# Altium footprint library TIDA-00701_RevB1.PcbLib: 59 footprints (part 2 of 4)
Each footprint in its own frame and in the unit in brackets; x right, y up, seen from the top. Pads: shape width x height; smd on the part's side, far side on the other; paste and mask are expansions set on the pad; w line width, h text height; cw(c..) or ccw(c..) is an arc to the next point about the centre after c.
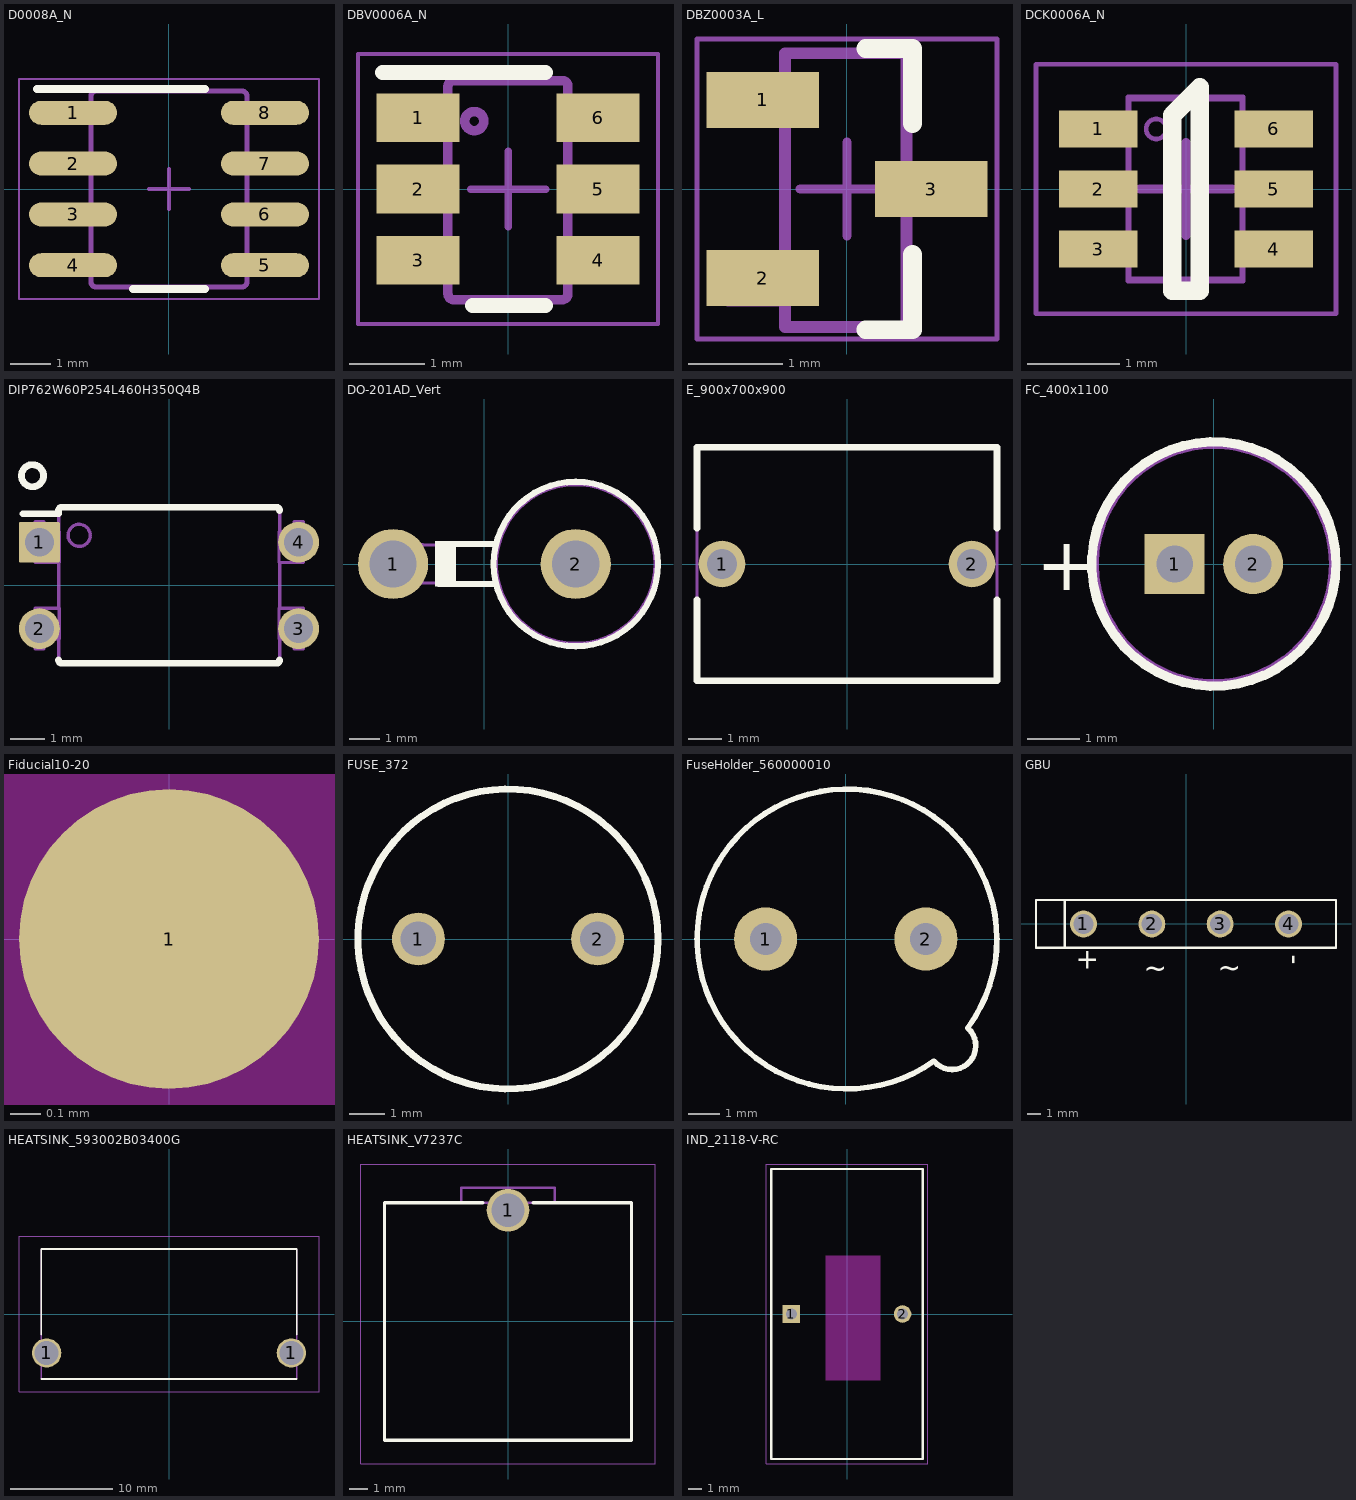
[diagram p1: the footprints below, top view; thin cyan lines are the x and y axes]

## D0008A_N [mm] "SOIC, 8-Leads, Body 4.9x3.9mm, Pitch 1.27mm, IPC Medium Density"
height 1.75
pads (8):
  oval 2.2x0.6 smd: 1(-2.4,1.905) 2(-2.4,0.635) 3(-2.4,-0.635) 4(-2.4,-1.905) 5(2.4,-1.905) 6(2.4,-0.635) 7(2.4,0.635) 8(2.4,1.905)
Top Overlay:
  lines w0.2: -3.3,2.5 0.9,2.5 ; -0.9,-2.5 0.9,-2.5
Mechanical 5:
  lines w0.127: -2.375,-2.095 -1.995,-2.095 -1.952,-2.095 -1.952,-1.715 -1.995,-1.715 -2.375,-1.715 ; -2.375,-2.095 -2.589,-2.095 -3.002,-2.095 -3.002,-1.715 -2.589,-1.715 -2.375,-1.715 ; -2.375,-2.095 -2.375,-1.715 ; -2.375,-0.825 -1.995,-0.825 -1.952,-0.825 -1.952,-0.445 -1.995,-0.445 -2.375,-0.445 ; -2.375,-0.825 -2.589,-0.825 -3.002,-0.825 -3.002,-0.445 -2.589,-0.445 -2.375,-0.445 ; -2.375,-0.825 -2.375,-0.445 ; -2.375,0.445 -1.995,0.445 -1.952,0.445 -1.952,0.825 -1.995,0.825 -2.375,0.825 ; -2.375,0.445 -2.589,0.445 -3.002,0.445 -3.002,0.825 -2.589,0.825 -2.375,0.825 ; -2.375,0.445 -2.375,0.825 ; -2.375,1.715 -1.995,1.715 -1.952,1.715 -1.952,2.095 -1.995,2.095 -2.375,2.095 ; -2.375,1.715 -2.589,1.715 -3.002,1.715 -3.002,2.095 -2.589,2.095 -2.375,2.095 ; -2.375,1.715 -2.375,2.095 ; -0.332,-2.45 -1.825,-2.45 -1.826,-2.45 cw(c-1.825,-2.323) -1.952,-2.324 -1.952,-2.323 -1.952,2.323 -1.952,2.324 cw(c-1.825,2.323) -1.826,2.45 -1.825,2.45 -0.332,2.45 ; -0.332,-2.45 -0.182,-2.45 ; -0.332,-2.45 -0.182,-2.45 ; -0.332,2.45 -0.182,2.45 ; -0.332,2.45 -0.182,2.45 ; -0.182,-2.45 0.178,-2.45 ; -0.182,2.45 0.178,2.45 ; 0.178,-2.45 0.328,-2.45 ; 0.178,-2.45 0.328,-2.45 ; 0.178,2.45 0.328,2.45 ; 0.178,2.45 0.328,2.45 ; 0.328,-2.45 1.821,-2.45 1.822,-2.45 ccw(c1.821,-2.323) 1.948,-2.324 1.948,-2.323 1.948,2.323 1.948,2.324 ccw(c1.821,2.323) 1.822,2.45 1.821,2.45 0.328,2.45 ; 2.371,-2.095 2.585,-2.095 2.998,-2.095 2.998,-1.715 2.585,-1.715 2.371,-1.715 ; 2.371,-2.095 1.991,-2.095 1.948,-2.095 1.948,-1.715 1.991,-1.715 2.371,-1.715 ; 2.371,-2.095 2.371,-1.715 ; 2.371,-0.825 2.585,-0.825 2.998,-0.825 2.998,-0.445 2.585,-0.445 2.371,-0.445 ; 2.371,-0.825 1.991,-0.825 1.948,-0.825 1.948,-0.445 1.991,-0.445 2.371,-0.445 ; 2.371,-0.825 2.371,-0.445 ; 2.371,0.445 2.585,0.445 2.998,0.445 2.998,0.825 2.585,0.825 2.371,0.825 ; 2.371,0.445 1.991,0.445 1.948,0.445 1.948,0.825 1.991,0.825 2.371,0.825 ; 2.371,0.445 2.371,0.825 ; 2.371,1.715 2.585,1.715 2.998,1.715 2.998,2.095 2.585,2.095 2.371,2.095 ; 2.371,1.715 1.991,1.715 1.948,1.715 1.948,2.095 1.991,2.095 2.371,2.095 ; 2.371,1.715 2.371,2.095
  text ".Designator" at 0.452,-0.439 h0.89
Mechanical 15:
  lines w0.05: -3.75,-2.75 -3.75,2.75 3.75,2.75 3.75,-2.75 -3.75,-2.75
  lines w0.1: -0.5,0 0.5,0 ; 0,-0.5 0,0.5
3D body: height 1.63, standoff 0, extent -3,-2.45 3,2.45

## DBV0006A_N [mm] "SOT23, 6-Leads, Body 2.9x1.6mm, Pitch 0.95mm, Lead Span 2.8mm, IPC Medium Density"
height 1.45
pads (6):
  rect 1.1x0.65 smd: 1(-1.2,0.95) 2(-1.2,0) 3(-1.2,-0.95) 4(1.2,-0.95) 5(1.2,0) 6(1.2,0.95)
Top Overlay:
  lines w0.2: -1.675,1.55 0.5,1.55 ; -0.475,-1.55 0.5,-1.55
Mechanical 5:
  lines w0.127: 0.724,-1.475 ccw(c0.723,-1.399) 0.8,-1.399 0.799,1.37 ccw(c0.723,1.37) 0.724,1.446 ; 0.723,-1.475 -0.725,-1.475 -0.725,-1.475 cw(c-0.724,-1.399) -0.801,-1.399 -0.801,1.37 cw(c-0.724,1.37) -0.725,1.446 -0.725,1.446 0.723,1.446 ; 0.723,-1.475 0.724,-1.475 ; 0.723,1.446 0.724,1.446 ; -1.423,-1.154 -1.423,-0.78 -1.206,-0.78 -1.113,-0.78 -1.081,-0.78 -0.828,-0.78 -0.801,-0.78 -0.801,-1.154 -0.828,-1.154 -1.081,-1.154 -1.113,-1.154 -1.206,-1.154 -1.423,-1.154 ; -1.423,-0.202 -1.423,0.173 -1.206,0.173 -1.113,0.173 -1.081,0.173 -0.828,0.173 -0.801,0.173 -0.801,-0.202 -0.828,-0.202 -1.081,-0.202 -1.113,-0.202 -1.206,-0.202 -1.423,-0.202 ; -1.423,0.751 -1.423,1.125 -1.206,1.125 -1.113,1.125 -1.081,1.125 -0.828,1.125 -0.801,1.125 -0.801,0.751 -0.828,0.751 -1.081,0.751 -1.113,0.751 -1.206,0.751 -1.423,0.751 ; -0.577,0.906 ccw(c-0.45,0.906) -0.323,0.906 ccw(c-0.45,0.906) -0.577,0.906 ; 0.799,-1.154 0.799,-0.78 0.827,-0.78 1.08,-0.78 1.112,-0.78 1.205,-0.78 1.422,-0.78 1.422,-1.154 1.205,-1.154 1.112,-1.154 1.08,-1.154 0.827,-1.154 0.799,-1.154 ; 0.799,-0.202 0.799,0.173 0.827,0.173 1.08,0.173 1.112,0.173 1.205,0.173 1.422,0.173 1.422,-0.202 1.205,-0.202 1.112,-0.202 1.08,-0.202 0.827,-0.202 0.799,-0.202 ; 0.799,0.751 0.799,1.125 0.827,1.125 1.08,1.125 1.112,1.125 1.205,1.125 1.422,1.125 1.422,0.751 1.205,0.751 1.112,0.751 1.08,0.751 0.827,0.751 0.799,0.751
  text ".Designator" at -0.356,0.457 h0.89
Mechanical 15:
  lines w0.05: -2,-1.8 2,-1.8 2,1.8 -2,1.8 -2,-1.8
  lines w0.1: -0.5,0 0.5,0 ; 0,-0.5 0,0.5
3D body: height 1.11, standoff -0.01, extent -1.422,-1.461 1.422,1.46

## DBZ0003A_L [mm] "SOT23, 3-Leads, Body 2.9x1.3mm, Pitch 0.95mm, Lead Span 2.4mm, IPC High Density"
height 1.12
pads (3):
  rect 1.2x0.6 smd: 1(-0.9,0.95) 2(-0.9,-0.95) 3(0.9,0)
Top Overlay:
  lines w0.2: 0.2,-1.5 0.7,-1.5 0.7,-0.7 ; 0.2,1.5 0.7,1.5 0.7,0.7
Mechanical 5:
  lines w0.127: -1.27,-1.187 -1.063,-1.187 -1.005,-1.187 -0.814,-1.187 -0.66,-1.187 -0.66,-0.743 -0.814,-0.743 -1.005,-0.743 -1.063,-0.743 -1.27,-0.743 -1.27,-1.187 ; -1.27,0.718 -1.063,0.718 -1.005,0.718 -0.814,0.718 -0.66,0.718 -0.66,1.162 -0.814,1.162 -1.005,1.162 -1.063,1.162 -1.27,1.162 -1.27,0.718 ; -0.66,-1.473 0.635,-1.473 0.635,1.448 -0.66,1.448 -0.66,-1.473 ; 0.635,-0.235 0.635,0.21 0.789,0.21 0.98,0.21 1.037,0.21 1.245,0.21 1.245,-0.235 1.037,-0.235 0.98,-0.235 0.789,-0.235 0.635,-0.235
  text ".Designator" at -0.457,0.635 h0.89
Mechanical 15:
  lines w0.05: -1.6,-1.6 -1.6,1.6 1.6,1.6 1.6,-1.6 -1.6,-1.6
  lines w0.1: -0.5,0 0.5,0 ; 0,-0.5 0,0.5
3D body: height 0.96, standoff -0.02, extent -1.257,-1.461 1.257,1.46

## DCK0006A_N [mm] "SOT23, 6-Leads, Body 2x1.3mm, Pitch 0.65mm, Lead Span 2.1mm, IPC Medium Density"
height 1.1
pads (6):
  rect 0.85x0.4 smd: 1(-0.95,0.65) 2(-0.95,0) 3(-0.95,-0.65) 4(0.95,-0.65) 5(0.95,0) 6(0.95,0.65)
Top Overlay:
  lines w0.2: -0.15,-1.1 0.15,-1.1 0.15,1.1 -0.15,0.8 -0.15,-1.1
Mechanical 5:
  lines w0.05: -0.613,-0.763 -0.613,-0.976 0.607,-0.976 0.607,-0.763 ; -0.613,-0.538 -0.613,-0.113 ; -0.613,0.112 -0.613,0.537 ; -0.613,0.762 -0.613,0.974 0.607,0.974 0.607,0.762 ; 0.607,-0.538 0.607,-0.113 ; 0.607,0.112 0.607,0.537 ; -0.628,-0.763 -0.591,-0.763 -0.591,-0.538 -0.628,-0.538 ; -0.628,-0.763 -0.853,-0.763 -0.865,-0.763 -0.959,-0.763 -1.143,-0.763 -1.143,-0.538 -0.959,-0.538 -0.865,-0.538 -0.853,-0.538 -0.628,-0.538 ; -0.628,-0.763 -0.628,-1.001 0.622,-1.001 0.622,-0.763 ; -0.628,-0.538 -0.628,-0.113 ; -0.628,-0.113 -0.591,-0.113 -0.591,0.112 -0.628,0.112 ; -0.628,-0.113 -0.853,-0.113 -0.865,-0.113 -0.959,-0.113 -1.143,-0.113 -1.143,0.112 -0.959,0.112 -0.865,0.112 -0.853,0.112 -0.628,0.112 ; -0.628,0.112 -0.628,0.537 ; -0.628,0.537 -0.591,0.537 -0.591,0.762 -0.628,0.762 ; -0.628,0.537 -0.853,0.537 -0.865,0.537 -0.959,0.537 -1.143,0.537 -1.143,0.762 -0.959,0.762 -0.865,0.762 -0.853,0.762 -0.628,0.762 ; -0.628,0.762 -0.628,0.999 0.622,0.999 0.622,0.762 ; 0.622,-0.763 0.585,-0.763 0.585,-0.538 0.622,-0.538 ; 0.622,-0.763 0.847,-0.763 0.859,-0.763 0.953,-0.763 1.137,-0.763 1.137,-0.538 0.953,-0.538 0.859,-0.538 0.847,-0.538 0.622,-0.538 ; 0.622,-0.538 0.622,-0.113 ; 0.622,-0.113 0.847,-0.113 0.859,-0.113 0.953,-0.113 1.137,-0.113 1.137,0.112 0.953,0.112 0.859,0.112 0.847,0.112 0.622,0.112 ; 0.622,-0.113 0.585,-0.113 0.585,0.112 0.622,0.112 ; 0.622,0.112 0.622,0.537 ; 0.622,0.537 0.585,0.537 0.585,0.762 0.622,0.762 ; 0.622,0.537 0.847,0.537 0.859,0.537 0.953,0.537 1.137,0.537 1.137,0.762 0.953,0.762 0.859,0.762 0.847,0.762 0.622,0.762 ; -0.432,0.65 ccw(c-0.323,0.65) -0.215,0.65 ccw(c-0.323,0.65) -0.432,0.65
  text ".Designator" at -1.524,-0.584 h0.89
Mechanical 15:
  lines w0.05: -1.625,-1.35 1.625,-1.35 1.625,1.35 -1.625,1.35 -1.625,-1.35
  lines w0.1: -0.5,0 0.5,0 ; 0,-0.5 0,0.5
3D body: height 0.94, standoff -0.01, extent -1.14,-1 1.14,1

## DIP762W60P254L460H350Q4B [mm] "LITE-ON"
height 4.5
pads (4):
  rrect8% 1.2x1.2 hole 0.85: 1(-3.81,1.27)
  round 1.2 hole 0.85: 2(-3.81,-1.27) 3(3.81,-1.27) 4(3.81,1.27)
Top Overlay:
  circle w0.2: c-4.013,3.226 r0.325
  lines w0.2: -4.293,2.108 -3.247,2.108 -3.247,2.201 cw(c-3.148,2.201) -3.148,2.3 3.154,2.3 cw(c3.154,2.201) 3.253,2.201 ; -3.247,-2.191 ccw(c-3.148,-2.192) -3.148,-2.29 3.154,-2.29 ccw(c3.154,-2.192) 3.253,-2.191
Mechanical 5:
  circle w0.1: c-2.642,1.473 r0.325
  lines w0.1: -3.677,-1.565 -3.677,-1.865 -3.937,-1.865 -3.937,-1.565 ; -3.677,1.575 -3.677,1.875 -3.937,1.875 -3.937,1.575 ; -3.247,-1.565 -3.247,-2.191 ccw(c-3.148,-2.192) -3.148,-2.29 3.154,-2.29 ccw(c3.154,-2.192) 3.253,-2.191 3.253,-1.565 ; -3.247,-0.665 -3.247,0.675 ; -3.247,1.575 -3.247,2.201 cw(c-3.148,2.201) -3.148,2.3 3.154,2.3 cw(c3.154,2.201) 3.253,2.201 3.253,1.575 ; 3.253,-0.665 3.253,0.675 ; 3.683,-1.565 3.683,-1.865 3.943,-1.865 3.943,-1.565 ; 3.683,1.575 3.683,1.875 3.943,1.875 3.943,1.575 ; -3.937,-1.565 -3.937,-0.665 -3.737,-0.665 -3.229,-0.665 -3.229,-1.565 -3.737,-1.565 -3.937,-1.565 ; -3.937,1.575 -3.937,0.675 -3.737,0.675 -3.229,0.675 -3.229,1.575 -3.737,1.575 -3.937,1.575 ; 3.943,-1.565 3.943,-0.665 3.743,-0.665 3.235,-0.665 3.235,-1.565 3.743,-1.565 3.943,-1.565 ; 3.943,1.575 3.743,1.575 3.235,1.575 3.235,0.675 3.743,0.675 3.943,0.675 3.943,1.575
  text ".Designator" at 0.406,-0.025 h0.89
3D body: height 4.3, standoff -2.7, extent -3.94,-2.295 3.94,2.295

## DO-201AD_Vert [mm] "DO-201AD VERTICAL FOOTPRINT"
height 14.5
pads (2):
  round 2.3 hole 1.55: 1(-3,0) 2(3,0)
Top Overlay:
  circle w0.2: c3,0 r2.7
  rectangle: -1.625,-0.744 -0.925,0.756
  lines w0.2: -1.5,-0.65 0.3,-0.65 ; -1.5,0.65 0.3,0.65
Mechanical 5:
  circle w0.1: c3,0 r2.6
  rectangle: -2.696,-0.659 -1.996,0.691
  lines w0.1: -3,-0.625 0.4,-0.625 ; -3,-0.6 -3,0.6 ; -2.975,0.625 0.425,0.625
  text ".Designator" at 3.277,0.127 h0.89
3D body: height 14.8, standoff -2.54, extent -3.659,-2.655 5.655,2.655

## E_900x700x900 [mm] "TH, 2- Leads, Body 9x7mm, Pin Spacing 7.5mm"
height 12
pads (2):
  round 1.4 hole 0.9: 1(-3.75,0) 2(3.75,0)
Top Overlay:
  lines w0.2: -4.5,-1.071 -4.5,-3.5 4.5,-3.5 4.5,-1.071 ; -4.5,1.071 -4.5,3.5 4.5,3.5 4.5,1.071
Mechanical 5:
  lines w0.1: -4.5,-3.5 -4.5,3.5 4.5,3.5 4.5,-3.5 -4.5,-3.5
  text ".Designator" at -1.397,-0.406 h0.89
3D body: height 11.96, standoff 3, extent -4.491,-3.5 4.491,3.5
3D body: height 0.3, standoff -2.5, extent 3.45,-0.299 4.048,0.299
3D body: height 1.36, standoff -0.16, extent 3.45,-0.299 4.048,1.732
3D body: height 6.12, standoff 0.81, extent 1.546,1.033 4.048,1.732
3D body: height 6.12, standoff 0.81, extent -4.047,-1.732 -1.545,-1.033
3D body: height 1.36, standoff -0.16, extent -4.047,-1.732 -3.45,0.3
3D body: height 0.3, standoff -2.5, extent -4.047,-0.299 -3.45,0.3

## FC_400x1100 [mm] "Panasonic"
height 12
pads (2):
  rect 1.15x1.15 hole 0.7: 1(-0.75,0)
  round 1.15 hole 0.7: 2(0.75,0)
Top Overlay:
  circle w0.18: c0,0 r2.335
  text "+" at -3.4,-0.5 h1.02
Mechanical 5:
  circle w0.1: c0,0 r2.25
  text "+" at -3.4,-0.5 h0.89
  text ".Designator" at -0.483,1.168 h0.89
3D body: height 12.01, standoff -4, extent -2.232,-2.246 2.252,2.246

## FCC_disclaimer [mm]

## Fiducial10-20 [mm]
pads (1):
  round 1 smd mask+0.5: 1(0,0)
Top Layer keep-out:
  circle w1.178: c0,0 r0.5

## FUSE_372 [mm] "LITTELFUSE"
height 8
pads (2):
  round 1.5 hole 1: 1(-2.54,0) 2(2.54,0)
Top Overlay:
  circle w0.2: c0,0 r4.25
Mechanical 5:
  circle w0.1: c0,0 r4.25
  text ".Designator" at -0.838,-0.559 h0.89
3D body: height 4, standoff -2, extent -2.837,-0.299 -2.24,0.3
3D body: height 4, standoff -2, extent 2.242,-0.299 2.84,0.299
3D body: height 8, standoff 0, extent -4.259,-4.259 4.259,4.259

## FuseHolder_560000010 [mm] "Littelfuse fuse holder TR5"
height 5.6
pads (2):
  round 2 hole 1: 1(-2.54,0) 2(2.54,0)
Top Overlay:
  lines w0.178: -4.71,-0.051 cw(c-4.212,0) -4.71,0.051 ; 4.79,-0.051 ccw(c4.292,0) 4.79,0.051 ; 2.797,-3.868 cw(c0.04,0) 3.863,-2.819 cw(c3.372,-3.386) 2.797,-3.868
Mechanical 5:
  lines w0.127: -4.71,-0.051 cw(c-4.212,0) -4.71,0.051 ; 4.79,-0.051 ccw(c4.292,0) 4.79,0.051 ; 2.797,-3.868 ccw(c3.372,-3.386) 3.863,-2.819 ccw(c0.04,0) 2.797,-3.868
  text ".Designator" at -6.807,-2.108 h0.89
3D body: height 5.6, standoff -3, extent -4.752,-4.737 4.752,4.75

## GBU [mm] "Comchip / Diodes Inc diode bridge"
height 21.55
pads (4):
  round 2 hole 1.5: 1(-7.62,0) 2(-2.54,0) 3(2.54,0) 4(7.62,0)
Top Overlay:
  lines w0.178: -9,-1.78 -9,1.78 ; -11.15,-1.78 -11.15,0 -11.15,1.78 0,1.78 11.15,1.78 11.15,0 11.15,-1.78 0,-1.78 -11.15,-1.78
  text "+" at -8.204,-3.327 h1.52
  text "-" at 8.585,-3.048 h1.52
  text "~" at -3.15,-4.013 h1.52
  text "~" at 2.362,-3.962 h1.52
Mechanical 5:
  lines w0.127: -9,-1.78 -9,1.78 ; -11.15,-1.78 -11.15,0 -11.15,1.78 0,1.78 11.15,1.78 11.15,0 11.15,-1.78 0,-1.78 -11.15,-1.78
  text ".Designator" at -0.737,-0.889 h0.89
  text "+" at -7.62,-0.254 h0.89
  text "-" at 7.722,-0.254 h0.89
  text "~" at -2.794,-0.711 h0.89
  text "~" at 2.311,-0.635 h0.89
3D body: height 21.55, standoff -15.25, extent -11.15,-1.76 11.15,1.8

## HEATSINK_593002B03400G [mm] "HEATSINK, 25X12.7X29.97 MM"
height 29.97
pads (2):
  round 2.868 hole 2.36: 1(-11.965,-3.81) 1(11.965,-3.81)
Top Overlay:
  lines w0.178: -12.5,-6.35 12.5,-6.35 ; -12.5,-2 -12.5,6.35 12.5,6.35 12.5,-2
  text ".Designator" at -13.843,3.099 h0.89
Mechanical 5:
  lines w0.127: -12.5,-6.35 -12.5,6.35 12.5,6.35 12.5,-6.35 -12.5,-6.35
  text ".Designator" at 12.725,1.93 h0.89
Mechanical 15:
  lines w0.05: -14.669,-7.62 -14.669,7.62 14.669,7.62 14.669,-7.62 -14.669,-7.62
Mechanical 17:
  text "LEAD LENGTH: 4.27 MM" at -9.652,2.286 h1
3D body: height 29.97, standoff 0, extent -12.5,-6.35 12.5,6.35

## HEATSINK_V7237C [mm] "HEATSINK,TO-220,13.21X12.7MM"
height 19.05
pads (1):
  round 2.28 hole 1.78: 1(0,5.95)
Top Overlay:
  lines w0.178: -1.342,6.35 -6.605,6.35 -6.605,-6.35 6.605,-6.35 6.605,6.35 1.342,6.35
  text ".Designator" at -2.87,-7.569 h0.89
Mechanical 5:
  lines w0.127: -2.5,6.35 -2.5,7.15 2.5,7.15 2.5,6.35 ; -6.605,-6.35 -6.605,6.35 6.605,6.35 6.605,-6.35 -6.605,-6.35
  text ".Designator" at -6.248,6.756 h0.89
Mechanical 15:
  lines w0.05: -7.875,-7.62 -7.875,8.42 7.875,8.42 7.875,-7.62 -7.875,-7.62
Mechanical 17:
  text "LEAD LENGTH: 6.35 MM" at -9.169,-2.515 h1
3D body: height 19.05, standoff 0, extent -6.605,-6.35 6.605,6.35

## IND_2118-V-RC [mil] "INDUCTOR,2 LEAD,VERTICAL MOUNT,8.382mm PITCH,TH"
height 860
pads (2):
  rect 52x52 / inner round 52 / far side rect 52x52 hole 32: 1(-165,0)
  round 52 hole 32.01: 2(165,0)
Top Layer keep-out:
  rectangle: -64,-196.86 100,173.99
Top Overlay:
  lines w7: -225,-430 -225,430 225,430 225,-430 -225,-430
  text ".Designator" at -239,231 h35
Mechanical 5:
  lines w5: -225,-430 225,-430 225,430 -225,430 -225,-430
  text ".Designator" at -25,-48 h35
Mechanical 15:
  lines w1.97: -240,-445 -240,445 240,445 240,-445 -240,-445
Mechanical 17:
  text "LEAD LENGTH:12.7MM" at -470,210 h60
3D body: height 860, standoff 0, extent -225,-430 225,430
